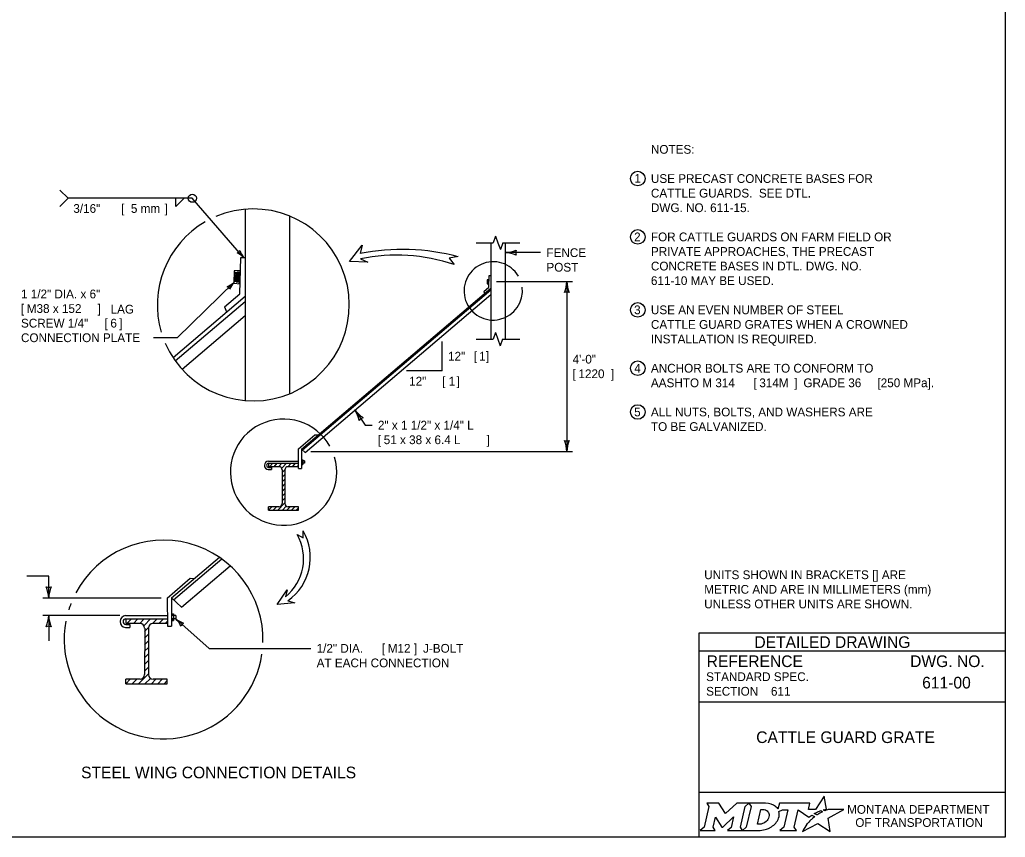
# Model space of a CAD drawing. Extents: x 49991.4 to 50021, y 49987.6 to 50011.4.
# Drawn here: x 50010 to 50016.75, y 49987.8 to 49993.4 of the extents above; entities that cross this region are included whole.
import ezdxf

# ---------------------------------------------------------------- set-up
doc = ezdxf.new("R2010")
doc.units = 0
for name, color, linetype in [('Default', 7, 'Continuous'), ('Level 1', 7, 'Continuous'), ('Level 2', 7, 'Continuous'), ('Level 3', 7, 'Continuous'), ('Level 4', 7, 'Continuous'), ('Level 5', 7, 'Continuous'), ('Level 6', 7, 'Continuous')]:
    doc.layers.add(name, color=color, linetype=linetype)

msp = doc.modelspace()

# ---------------------------------------------------------------- linework, layer by layer
at = {"layer": 'Default'}
for points in [[(50015.5126, 49987.9811), (50015.5023, 49987.9867), (50015.5139, 49987.9895), (50015.5255, 49987.9915), (50015.5081, 49988.0816), (50015.4486, 49987.9903), (50015.4013, 49987.9896), (50015.4116, 49988.0337), (50015.2024, 49988.0338), (50015.1923, 49987.9913), (50015.1865, 49987.9996)], [(50014.7056, 49988.0338), (50014.7197, 49988.0104), (50014.6862, 49987.8671), (50014.6605, 49987.8446), (50014.7621, 49987.8446), (50014.7486, 49987.8674), (50014.7648, 49987.9375), (50014.8085, 49987.8685), (50014.8138, 49987.8685), (50014.8889, 49987.938), (50014.8725, 49987.8669), (50014.8478, 49987.8449), (50014.9494, 49987.8449), (50014.9356, 49987.8682), (50014.9688, 49988.0106)], [(50014.9688, 49988.0106), (50014.9941, 49988.0338), (50014.9117, 49988.0338), (50014.8321, 49987.9608), (50014.7876, 49988.0335), (50014.7056, 49988.0338)], [(50015.1077, 49988.0338), (50014.9941, 49988.0338), (50015.0088, 49988.0109), (50014.9749, 49987.8671), (50014.9494, 49987.8449), (50015.06, 49987.8449)], [(50015.1317, 49987.9471), (50015.1305, 49987.939), (50015.1273, 49987.9297), (50015.1231, 49987.9215), (50015.1175, 49987.914), (50015.111, 49987.9071), (50015.1031, 49987.9008), (50015.0948, 49987.8961), (50015.0857, 49987.8922), (50015.0766, 49987.8899), (50015.0674, 49987.889), (50015.0515, 49987.889), (50015.0751, 49987.989), (50015.0911, 49987.989), (50015.0987, 49987.9884), (50015.1063, 49987.9865), (50015.1129, 49987.9835), (50015.119, 49987.9793), (50015.1238, 49987.9743), (50015.1275, 49987.9683), (50015.1302, 49987.9621), (50015.1318, 49987.9547), (50015.1318, 49987.9517), (50015.1317, 49987.9471)], [(50015.1991, 49987.9747), (50015.2237, 49987.9878), (50015.2606, 49987.9878), (50015.232, 49987.8673), (50015.2045, 49987.8446), (50015.3207, 49987.8446), (50015.3037, 49987.8675), (50015.3319, 49987.9877), (50015.4032, 49987.936), (50015.4243, 49987.9511), (50015.444, 49987.9402)], [(50015.3882, 49987.8843), (50015.3729, 49987.8599), (50015.3682, 49987.8524), (50015.3624, 49987.8438), (50015.3601, 49987.8395), (50015.4654, 49987.8926), (50015.5493, 49987.8375), (50015.5362, 49987.9302), (50015.6431, 49987.9886), (50015.5938, 49987.9894), (50015.5637, 49987.9898), (50015.5429, 49987.9901), (50015.5361, 49987.9886), (50015.5312, 49987.9874), (50015.5228, 49987.9851), (50015.5126, 49987.9811)], [(50015.4622, 49987.9535), (50015.4598, 49987.9518), (50015.4415, 49987.9614), (50015.4518, 49987.9671), (50015.4559, 49987.9693), (50015.4645, 49987.9733), (50015.4702, 49987.9759), (50015.4781, 49987.9789), (50015.4854, 49987.9816), (50015.4972, 49987.9742), (50015.4932, 49987.9721), (50015.4886, 49987.9696), (50015.4844, 49987.9674), (50015.4794, 49987.9645), (50015.4775, 49987.9634), (50015.4748, 49987.9618), (50015.4723, 49987.9604), (50015.47, 49987.9588), (50015.4674, 49987.957), (50015.4647, 49987.9552), (50015.4622, 49987.9535)], [(50015.1057, 49987.8522), (50015.1141, 49987.8548), (50015.1271, 49987.8602), (50015.1475, 49987.8712)], [(50015.4021, 49987.9004), (50015.4021, 49987.9004)]]:
    msp.add_lwpolyline(points, dxfattribs=at)
for centre, radius, start, end in [((50015.1308, 49987.9554), 0.0709, 339.53292, 15.85821), ((50015.0868, 49987.9727), 0.1183, 300.91025, 339.13831)]:
    msp.add_arc(centre, radius, start, end, dxfattribs=at)
for centre, major_axis, ratio, start_param, end_param in [((50015.1056, 49987.9864), (0.0834, -0.0037), 0.568097, 0.61298, 1.570796), ((50015.1612, 49987.9937), (0.0361, -0.0295), 0.469099, 1.225588, 1.570796), ((50015.4119, 49987.9106), (-0.0098, -0.0102), 0.016458, 3.141593, 6.279097), ((50015.4329, 49987.9305), (-0.0112, -0.0097), 0.021651, 3.157348, 6.283185), ((50015.0603, 49987.9932), (0, 0.1484), 0.987302, 3.139398, 3.456847), ((50015.3952, 49987.8923), (-0.00694, -0.00806), 0.008222, 0, 3.137361)]:
    msp.add_ellipse(centre, major_axis=major_axis, ratio=ratio, start_param=start_param, end_param=end_param, dxfattribs=at)
at = {"layer": 'Level 1'}
for p, q in [((50011.543, 49992.1026), (50011.5419, 49990.7922)), ((50011.8461, 49992.0563), (50011.8455, 49990.8382)), ((50013.2246, 49991.8724), (50013.2242, 49991.2135)), ((50013.3236, 49991.8724), (50013.3234, 49991.2135)), ((50011.5058, 49991.5236), (50011.5129, 49991.7728)), ((50011.5129, 49991.7728), (50011.5428, 49991.7726)), ((50011.467, 49991.6804), (50011.4643, 49991.5966)), ((50011.5104, 49991.6821), (50011.467, 49991.6804)), ((50011.4722, 49991.6743), (50011.4673, 49991.6057)), ((50011.4807, 49991.6707), (50011.4762, 49991.6057)), ((50011.4869, 49991.6741), (50011.4848, 49991.599)), ((50011.4898, 49991.6771), (50011.4946, 49991.6048)), ((50011.4992, 49991.6769), (50011.4995, 49991.5956)), ((50013.2124, 49991.5679), (50013.2148, 49991.6493)), ((50013.2148, 49991.6493), (50013.2245, 49991.6492)), ((50011.4643, 49991.5966), (50011.5078, 49991.5919)), ((50011.927, 49990.4596), (50013.2245, 49991.5632)), ((50013.178, 49991.5384), (50013.2124, 49991.5679)), ((50013.1998, 49991.6191), (50013.199, 49991.5917)), ((50013.199, 49991.5917), (50013.2131, 49991.5901)), ((50013.214, 49991.6197), (50013.1998, 49991.6191)), ((50013.2015, 49991.6174), (50013.1998, 49991.5947)), ((50013.2042, 49991.6159), (50013.2028, 49991.5946)), ((50013.2062, 49991.6171), (50013.2056, 49991.5925)), ((50013.2072, 49991.618), (50013.2088, 49991.5944)), ((50013.2102, 49991.6179), (50013.2104, 49991.5914)), ((50011.048, 49991.0869), (50011.5425, 49991.5079)), ((50011.4005, 49991.4332), (50011.5058, 49991.5236)), ((50011.952, 49990.4369), (50013.2244, 49991.5191)), ((50013.178, 49991.5384), (50013.1827, 49991.5277)), ((50011.4005, 49991.4332), (50011.4152, 49991.3995)), ((50011.1099, 49991.0067), (50011.5424, 49991.3741)), ((50011.9064, 49990.4618), (50012.0184, 49990.5571)), ((50012.0184, 49990.5571), (50012.0409, 49990.5564)), ((50011.9074, 49990.3253), (50011.9064, 49990.4618)), ((50011.927, 49990.4596), (50011.928, 49990.3257)), ((50011.927, 49990.4596), (50011.952, 49990.4369)), ((50011.7014, 49990.3776), (50011.907, 49990.3776)), ((50011.7024, 49990.3619), (50011.9072, 49990.3619)), ((50011.7024, 49990.3619), (50011.7024, 49990.3388)), ((50011.7731, 49990.3386), (50011.7024, 49990.3388)), ((50011.7082, 49990.3388), (50011.7307, 49990.3619)), ((50011.7398, 49990.3387), (50011.7622, 49990.3619)), ((50011.7711, 49990.3387), (50011.7936, 49990.3619)), ((50011.7923, 49990.328), (50011.825, 49990.3619)), ((50011.8341, 49990.3386), (50011.8566, 49990.3619)), ((50011.9073, 49990.3388), (50011.8366, 49990.3388)), ((50011.8656, 49990.3388), (50011.888, 49990.3619)), ((50011.897, 49990.3388), (50011.9073, 49990.3492)), ((50011.9276, 49990.3857), (50011.938, 49990.3859)), ((50011.9276, 49990.3811), (50011.938, 49990.3814)), ((50011.9486, 49990.3783), (50011.9276, 49990.3781)), ((50011.9484, 49990.362), (50011.9278, 49990.3618)), ((50011.9278, 49990.3575), (50011.938, 49990.3576)), ((50011.9278, 49990.353), (50011.938, 49990.353)), ((50011.938, 49990.3859), (50011.938, 49990.353)), ((50011.9486, 49990.3783), (50011.9484, 49990.362)), ((50011.7005, 49990.3183), (50011.7224, 49990.3185)), ((50011.702, 49990.334), (50011.7224, 49990.334)), ((50011.7224, 49990.334), (50011.7224, 49990.3185)), ((50011.7954, 49990.2989), (50011.8141, 49990.3182)), ((50011.7954, 49990.3162), (50011.7957, 49990.0863)), ((50011.7955, 49990.2664), (50011.8141, 49990.2856)), ((50011.814, 49990.3162), (50011.8143, 49990.0863)), ((50011.9074, 49990.3253), (50011.928, 49990.3257)), ((50011.7955, 49990.234), (50011.8141, 49990.2531)), ((50011.7955, 49990.2016), (50011.8141, 49990.2208)), ((50011.7956, 49990.1691), (50011.8142, 49990.1884)), ((50011.7956, 49990.1368), (50011.8142, 49990.156)), ((50011.7656, 49990.0408), (50011.8143, 49990.0911)), ((50011.7956, 49990.1043), (50011.8142, 49990.1238)), ((50011.797, 49990.0408), (50011.8235, 49990.068)), ((50011.7024, 49990.0408), (50011.7024, 49990.0638)), ((50011.7731, 49990.0637), (50011.7024, 49990.0638)), ((50011.7024, 49990.0408), (50011.9072, 49990.0408)), ((50011.7026, 49990.0408), (50011.725, 49990.0638)), ((50011.734, 49990.0408), (50011.7564, 49990.0637)), ((50011.8284, 49990.0408), (50011.8507, 49990.0637)), ((50011.9072, 49990.0638), (50011.8369, 49990.0637)), ((50011.86, 49990.0408), (50011.8822, 49990.0637)), ((50011.8914, 49990.0408), (50011.9072, 49990.0571)), ((50011.9072, 49990.0408), (50011.9072, 49990.0638)), ((50011.0365, 49989.4389), (50011.3653, 49989.7182)), ((50011.1065, 49989.376), (50011.4398, 49989.6598)), ((50011.0076, 49989.4386), (50011.1663, 49989.5736)), ((50011.1663, 49989.5736), (50011.1941, 49989.5728)), ((50011.0076, 49989.4386), (50011.009, 49989.2456)), ((50011.0365, 49989.4389), (50011.0377, 49989.2461)), ((50011.0365, 49989.4389), (50011.1065, 49989.376)), ((50011.0372, 49989.3296), (50011.0516, 49989.3298)), ((50011.0516, 49989.3298), (50011.0514, 49989.2841)), ((50010.7231, 49989.3182), (50011.0085, 49989.3183)), ((50010.7233, 49989.2577), (50010.7516, 49989.2577)), ((50010.7239, 49989.2965), (50011.0087, 49989.2965)), ((50010.7239, 49989.2965), (50010.7239, 49989.2644)), ((50010.822, 49989.2644), (50010.7239, 49989.2644)), ((50010.7322, 49989.2644), (50010.7633, 49989.2965)), ((50010.7516, 49989.2577), (50010.7516, 49989.236)), ((50010.7759, 49989.2644), (50010.8071, 49989.2965)), ((50010.8196, 49989.2644), (50010.8508, 49989.2965)), ((50010.8489, 49989.2493), (50010.8945, 49989.2965)), ((50010.9069, 49989.2642), (50010.9383, 49989.2965)), ((50011.0089, 49989.2644), (50010.9106, 49989.2644)), ((50010.9508, 49989.2644), (50010.9821, 49989.2965)), ((50010.9946, 49989.2644), (50011.0088, 49989.2789)), ((50011.0373, 49989.3232), (50011.0516, 49989.3236)), ((50011.0663, 49989.3193), (50011.0373, 49989.3189)), ((50011.066, 49989.2966), (50011.0374, 49989.2963)), ((50011.0375, 49989.2904), (50011.0515, 49989.2905)), ((50011.0375, 49989.2841), (50011.0514, 49989.2841)), ((50011.0663, 49989.3193), (50011.066, 49989.2966)), ((50010.7218, 49989.2359), (50010.7516, 49989.236)), ((50010.8535, 49989.233), (50010.8533, 49988.9134)), ((50010.8534, 49989.209), (50010.8793, 49989.2356)), ((50010.8534, 49989.1638), (50010.8792, 49989.1903)), ((50010.8792, 49989.233), (50010.8793, 49988.9134)), ((50011.009, 49989.2456), (50011.0377, 49989.2461)), ((50010.8534, 49989.1186), (50010.8793, 49989.1451)), ((50010.8534, 49989.0737), (50010.8793, 49989.1)), ((50010.8534, 49989.0283), (50010.8793, 49989.055)), ((50010.8534, 49988.9833), (50010.8793, 49989.0099)), ((50010.8117, 49988.8501), (50010.8793, 49988.9197)), ((50010.8533, 49988.9381), (50010.8793, 49988.9648)), ((50010.7239, 49988.8501), (50010.7239, 49988.882)), ((50010.8219, 49988.882), (50010.7239, 49988.882)), ((50010.7242, 49988.8501), (50010.7552, 49988.882)), ((50010.7679, 49988.8501), (50010.799, 49988.882)), ((50010.8556, 49988.8501), (50010.8923, 49988.888)), ((50010.8993, 49988.8501), (50010.93, 49988.882)), ((50011.0087, 49988.882), (50010.9108, 49988.882)), ((50010.9429, 49988.8501), (50010.9739, 49988.882)), ((50010.9866, 49988.8501), (50011.0087, 49988.8727)), ((50011.0087, 49988.8501), (50011.0087, 49988.882)), ((50010.7239, 49988.8501), (50011.0087, 49988.8501))]:
    msp.add_line(p, q, dxfattribs=at)
msp.add_lwpolyline([(49999.3835, 49998.9992), (50016.7501, 49998.9992), (50016.7501, 49987.7988), (49999.3835, 49987.7988)], close=True, dxfattribs=at)
for centre, radius, start, end in [((50011.7033, 49990.3479), 0.0297, 93.66122, 264.44873), ((50011.7033, 49990.3479), 0.014, 93.66122, 264.44873), ((50011.7735, 49990.3167), 0.0219, 358.50028, 91.21224), ((50011.8366, 49990.3162), 0.0226, 90, 180), ((50011.7731, 49990.0863), 0.0226, 270, 0), ((50011.8369, 49990.0863), 0.0226, 180, 270), ((50010.7258, 49989.277), 0.0413, 93.66122, 264.44873), ((50010.7252, 49989.2771), 0.0195, 93.66122, 264.44873), ((50010.822, 49989.233), 0.0314, 0, 90), ((50010.9106, 49989.233), 0.0314, 90, 180), ((50010.8219, 49988.9134), 0.0314, 270, 0), ((50010.9108, 49988.9134), 0.0314, 180, 270)]:
    msp.add_arc(centre, radius, start, end, dxfattribs=at)
at = {"layer": 'Level 2'}
for centre in [(50014.2321, 49992.3135), (50014.2321, 49991.9135), (50014.2321, 49991.4135), (50014.2321, 49991.0135), (50014.2321, 49990.7135)]:
    msp.add_circle(centre, 0.05, dxfattribs=at)
at = {"layer": 'Level 3'}
for p, q in [((50010.2723, 49992.2343), (50010.3283, 49992.1783)), ((50010.2723, 49992.1223), (50010.3283, 49992.1783)), ((50011.18, 49992.1783), (50010.3283, 49992.1783)), ((50011.0679, 49992.1223), (50011.0679, 49992.1783)), ((50011.0679, 49992.1223), (50011.1239, 49992.1783)), ((50011.5315, 49991.7727), (50011.18, 49992.1783)), ((50012.2566, 49991.7455), (50012.3442, 49991.856)), ((50012.3442, 49991.856), (50012.3299, 49991.799)), ((50012.3326, 49991.7629), (50012.383, 49991.7403)), ((50013.5662, 49991.8055), (50013.3236, 49991.8055)), ((50012.383, 49991.7403), (50012.2566, 49991.7455)), ((50012.9732, 49991.7237), (50012.9732, 49991.7235)), ((50011.4645, 49991.6008), (50011.0763, 49991.2226)), ((50013.2644, 49991.6084), (50013.7859, 49991.6084)), ((50013.7459, 49991.6084), (50013.7459, 49990.4426)), ((50011.0763, 49991.2226), (50010.9147, 49991.2224)), ((50012.892, 49990.995), (50012.892, 49991.1967)), ((50012.892, 49990.995), (50012.6479, 49990.995)), ((50012.892, 49990.995), (50012.6479, 49990.995)), ((50012.294, 49990.7278), (50012.3652, 49990.6232)), ((50012.3652, 49990.6232), (50012.4116, 49990.6232)), ((50011.992, 49990.4426), (50012.9422, 49990.4426)), ((50012.9422, 49990.4426), (50013.3408, 49990.4426)), ((50013.3408, 49990.4426), (50013.7859, 49990.4426)), ((50011.898, 49989.874), (50011.9392, 49989.852)), ((50011.9392, 49989.852), (50011.9392, 49989.8986)), ((50010.1957, 49989.5886), (50010.0457, 49989.5886)), ((50010.1957, 49989.4386), (50010.1957, 49989.5886)), ((50010.1957, 49989.4386), (50010.1957, 49989.5886)), ((50011.7608, 49989.3953), (50011.8294, 49989.4938)), ((50011.8294, 49989.4938), (50011.8184, 49989.4472)), ((50010.9676, 49989.4386), (50010.1557, 49989.4386)), ((50011.8816, 49989.4063), (50011.7608, 49989.3953)), ((50011.8348, 49989.42), (50011.8816, 49989.4063)), ((50010.6831, 49989.3182), (50010.1557, 49989.3182)), ((50010.1957, 49989.3182), (50010.1957, 49989.1448)), ((50011.066, 49989.2966), (50011.2956, 49989.0938)), ((50011.2956, 49989.0938), (50011.9917, 49989.0938))]:
    msp.add_line(p, q, dxfattribs=at)
msp.add_lwpolyline([(50013.0005, 49991.7781), (50012.9402, 49991.7683), (50012.9732, 49991.7237)], dxfattribs=at)
msp.add_circle((50011.1799, 49992.1784), 0.028, dxfattribs=at)
for centre, radius, start, end in [((50011.5979, 49991.4474), 0.6576, 203.48663, 113.08752), ((50011.5979, 49991.4474), 0.6576, 120.0594, 196.51475), ((50012.6204, 49990.3455), 1.4821, 75.12992, 101.29631), ((50011.4727, 49991.8405), 0.0383, 293.07387, 328.79623), ((50011.4137, 49991.6599), 0.1631, 43.76236, 63.01221), ((50011.6531, 49991.8697), 0.1556, 198.39106, 218.57457), ((50012.5823, 49990.5932), 1.196, 70.91589, 102.04542), ((50013.3121, 49992.0382), 0.233, 272.82731, 292.07716), ((50013.3145, 49991.5834), 0.2223, 67.45601, 87.63952), ((50013.4518, 49991.8055), 0.0548, 162.13882, 197.86118), ((50013.2418, 49991.5432), 0.2, 30.50645, 7.54977), ((50011.3606, 49991.7166), 0.1556, 291.70772, 311.89122), ((50011.4002, 49991.5381), 0.0383, 26.39052, 62.11289), ((50011.5839, 49991.4897), 0.1631, 137.07902, 156.32887), ((50013.5237, 49991.6176), 0.2223, 337.45601, 357.63952), ((50013.9786, 49991.6199), 0.233, 182.82731, 202.07716), ((50013.7459, 49991.4802), 0.0548, 72.13882, 107.86118), ((50012.1052, 49990.6104), 0.2223, 11.67911, 31.86261), ((50012.48, 49990.8681), 0.233, 217.05041, 236.30026), ((50011.805, 49990.3012), 0.3641, 29.15456, 16.55959), ((50012.3661, 49990.6217), 0.0548, 106.36191, 142.08427), ((50013.7459, 49990.5708), 0.0548, 252.13882, 287.86118), ((50013.5132, 49990.4311), 0.233, 2.82731, 22.07716), ((50013.968, 49990.4334), 0.2223, 157.45601, 177.63952), ((50011.6062, 49989.7075), 0.3361, 309.20704, 29.66003), ((50011.6255, 49989.7162), 0.363, 305.26654, 30.1427), ((50010.9832, 49989.1544), 0.6811, 358.26153, 151.97206), ((50010.1957, 49989.5668), 0.0548, 252.13882, 287.86118), ((50009.963, 49989.4271), 0.233, 2.82731, 22.07716), ((50010.1957, 49989.5668), 0.0548, 252.13882, 287.86118), ((50009.963, 49989.4271), 0.233, 2.82731, 22.07716), ((50010.4179, 49989.4294), 0.2223, 157.45601, 177.63952), ((50010.4179, 49989.4294), 0.2223, 157.45601, 177.63952), ((50010.9832, 49989.1544), 0.6811, 158.70281, 162.71537), ((50009.9736, 49989.3274), 0.2223, 337.45601, 357.63952), ((50010.4285, 49989.3297), 0.233, 182.82731, 202.07716), ((50010.9832, 49989.1544), 0.6811, 169.44578, 351.53112), ((50010.9433, 49989.1679), 0.1779, 26.18134, 46.36485), ((50011.1819, 49989.4426), 0.1864, 231.55264, 250.80249), ((50011.1431, 49989.2289), 0.0438, 120.86415, 156.58651), ((50010.1957, 49989.19), 0.0548, 72.13882, 107.86118)]:
    msp.add_arc(centre, radius, start, end, dxfattribs=at)
at = {"layer": 'Level 4'}
for p, q in [((50011.9341, 49990.4532), (50013.2244, 49991.5508)), ((50011.0635, 49991.0643), (50011.5425, 49991.4712)), ((50011.0512, 49989.4257), (50011.3817, 49989.7067))]:
    msp.add_line(p, q, dxfattribs=at)
at = {"layer": 'Level 5'}
for p, q in [((50016.7501, 49989.1988), (50014.6501, 49989.1988)), ((50014.6501, 49989.1988), (50014.6501, 49987.7988)), ((50016.7501, 49989.0738), (50014.6501, 49989.0738)), ((50016.3862, 49988.8587), (50016.3862, 49988.8587)), ((50015.1444, 49988.7993), (50015.1444, 49988.7993)), ((50016.7501, 49988.7238), (50014.6501, 49988.7238)), ((50015.7001, 49988.4747), (50015.7001, 49988.4747)), ((50016.7501, 49988.1057), (50014.6501, 49988.1057))]:
    msp.add_line(p, q, dxfattribs=at)
at = {"layer": 'Level 6'}
for p, q in [((50013.258, 49991.9181), (50013.2418, 49991.8724)), ((50013.258, 49991.9181), (50013.2742, 49991.8724)), ((50013.1246, 49991.8724), (50013.2418, 49991.8724)), ((50013.2742, 49991.8724), (50013.2904, 49991.8267)), ((50013.3066, 49991.8724), (50013.2904, 49991.8267)), ((50013.3066, 49991.8724), (50013.4236, 49991.8724)), ((50013.2576, 49991.2592), (50013.2414, 49991.2135)), ((50013.2576, 49991.2592), (50013.2738, 49991.2135)), ((50013.1242, 49991.2135), (50013.2414, 49991.2135)), ((50013.2738, 49991.2135), (50013.29, 49991.1678)), ((50013.3062, 49991.2135), (50013.29, 49991.1678)), ((50013.3062, 49991.2135), (50013.4234, 49991.2135))]:
    msp.add_line(p, q, dxfattribs=at)

# ---------------------------------------------------------------- texts
at = {"layer": 'Default'}
for s, p in [('MONTANA DEPARTMENT', (50015.6663, 49987.96)), ('OF TRANSPORTATION', (50015.7225, 49987.87))]:
    msp.add_text(s, height=0.06, dxfattribs=at).set_placement(p)
at = {"layer": 'Level 2'}
for s, height, p in [('NOTES:', 0.06, (50014.3221, 49992.4834)), ('1', 0.06, (50014.2093, 49992.2848)), ('USE PRECAST CONCRETE BASES FOR', 0.06, (50014.3221, 49992.2834)), ('CATTLE GUARDS.  SEE DTL.', 0.06, (50014.3221, 49992.1834)), (' 3/16" ', 0.06, (50010.3422, 49992.0783)), ('[', 0.06, (50010.6928, 49992.0783)), ('5 mm', 0.06, (50010.7591, 49992.0783)), (']', 0.06, (50010.9904, 49992.0783)), ('DWG. NO. 611-15.', 0.06, (50014.3221, 49992.0834)), ('2', 0.06, (50014.2069, 49991.8835)), ('FOR CATTLE GUARDS ON FARM FIELD OR', 0.06, (50014.3221, 49991.8835)), ('FENCE', 0.06, (50013.6062, 49991.7755)), ('PRIVATE APPROACHES, THE PRECAST', 0.06, (50014.3221, 49991.7835)), ('POST', 0.06, (50013.6062, 49991.6755)), ('CONCRETE BASES IN DTL. DWG. NO.', 0.06, (50014.3221, 49991.6835)), ('611-10 MAY BE USED.', 0.06, (50014.3221, 49991.5835)), ('1 1/2" DIA. x 6"', 0.06, (50010.006, 49991.4924)), ('[', 0.06, (50010.006, 49991.3924)), ('M38 x 152', 0.06, (50010.0457, 49991.3924)), ('] ', 0.06, (50010.5304, 49991.3924)), ('LAG', 0.06, (50010.62, 49991.388)), ('3', 0.06, (50014.2069, 49991.3835)), ('USE AN EVEN NUMBER OF STEEL', 0.06, (50014.3221, 49991.3835)), ('SCREW 1/4" ', 0.06, (50010.006, 49991.2924)), ('[', 0.06, (50010.5787, 49991.2924)), ('6', 0.06, (50010.6184, 49991.2924)), (']', 0.06, (50010.6784, 49991.2924)), ('CATTLE GUARD GRATES WHEN A CROWNED', 0.06, (50014.3221, 49991.2835)), ('CONNECTION PLATE', 0.06, (50010.006, 49991.1924)), ('INSTALLATION IS REQUIRED.', 0.06, (50014.3221, 49991.1835)), ('12" ', 0.06, (50012.932, 49991.0659)), ('[', 0.06, (50013.1085, 49991.0666)), ('1', 0.06, (50013.1446, 49991.0659)), (']', 0.06, (50013.1916, 49991.0673)), ('4\'-0"', 0.06, (50013.7859, 49991.0455)), ('4', 0.06, (50014.2081, 49990.9835)), ('ANCHOR BOLTS ARE TO CONFORM TO', 0.06, (50014.3221, 49990.9835)), ('12" ', 0.06, (50012.6657, 49990.895)), ('[', 0.06, (50012.8912, 49990.895)), ('1', 0.06, (50012.9363, 49990.895)), (']', 0.06, (50012.9909, 49990.895)), ('[', 0.06, (50013.7859, 49990.9455)), ('1220', 0.06, (50013.8256, 49990.9455)), (']', 0.06, (50014.0469, 49990.9455)), ('[', 0.06, (50015.0251, 49990.8835)), (']', 0.06, (50015.3048, 49990.8835)), ('[250 MPa].', 0.06, (50015.8743, 49990.8835)), ('AASHTO M 314 ', 0.06, (50014.3221, 49990.8835)), ('314M', 0.06, (50015.0648, 49990.8835)), (' GRADE 36 ', 0.06, (50015.3445, 49990.8835)), ('5', 0.06, (50014.2071, 49990.6835)), ('ALL NUTS, BOLTS, AND WASHERS ARE', 0.06, (50014.3221, 49990.6835)), ('2" x 1 1/2" x 1/4" L', 0.06, (50012.4516, 49990.5932)), ('TO BE GALVANIZED.', 0.06, (50014.3221, 49990.5835)), ('[', 0.06, (50012.4516, 49990.4932)), ('51 x 38 x 6.4 L', 0.06, (50012.4913, 49990.4932)), (']', 0.06, (50013.1962, 49990.4932)), ('UNITS SHOWN IN BRACKETS [] ARE ', 0.06, (50014.6872, 49989.568)), ('METRIC AND ARE IN MILLIMETERS (mm) ', 0.06, (50014.6872, 49989.468)), ('UNLESS OTHER UNITS ARE SHOWN.', 0.06, (50014.6872, 49989.368)), ('1/2" DIA. ', 0.06, (50012.0317, 49989.0638)), ('[', 0.06, (50012.4792, 49989.0638)), ('M12', 0.06, (50012.5188, 49989.0638)), (']', 0.06, (50012.6988, 49989.0638)), (' J-BOLT', 0.06, (50012.7385, 49989.0638)), ('AT EACH CONNECTION', 0.06, (50012.0317, 49988.9638)), ('611-00', 0.08, (50016.1806, 49988.8187)), ('611', 0.06, (50015.1444, 49988.7693)), ('CATTLE GUARD GRATE', 0.08, (50015.0434, 49988.4448)), ('STEEL WING CONNECTION DETAILS', 0.08, (50010.4179, 49988.203))]:
    msp.add_text(s, height=height, dxfattribs=at).set_placement(p)
at = {"layer": 'Level 5'}
for s, height, p in [('DETAILED DRAWING', 0.0799, (50015.0311, 49989.0963)), ('REFERENCE', 0.08, (50014.7037, 49988.9654)), ('DWG. NO.', 0.08, (50016.0979, 49988.9654)), ('STANDARD SPEC.', 0.06, (50014.7004, 49988.8694)), ('SECTION', 0.06, (50014.7004, 49988.7694))]:
    msp.add_text(s, height=height, dxfattribs=at).set_placement(p)

doc.saveas('drawing.dxf')
